(* Logix 5000 project; controller AMCI_3601_generic_sample_RSLogix_V28 vendor 1 type 14 code 108 rev 28.11; software revision 28.00 *)

TASK MainTask (continuous, watchdog 500 ms) : MainProgram

MODULES
   Local : vendor 1 type 14 code 108 (Compact 0, rev 28.11)
      AMCI_3601 : 1769-MODULE (Compact 1, rev 1.1, Output RPI 2 ms)
           Local:1:I.Data[3]   // AMCI 3601 lower current position
           Local:1:I.Data[2]   // AMCI 3601 upper current position
           Local:1:O.Data[1].9   // Blend Move Transmit bit
           Local:1:O.Data[0]   // AMCI 3601 module
END_MODULES

VAR_GLOBAL   (* controller tags *)
   blend_counter_3601 : COUNTER := (PRE := 6);   // control which blend segment is output to the 3601 module
        .PRE   // controls which blend programming block is output to the 3601 module
        .ACC   // controls which programming block is output
   blend_run_3601 : INT[8] := ([0] := 4096);
        [0]   // Run Blend Profile in the Positive Direction
   blend_segments_3601 : INT[17,8];
        [0,2]   // Number of segments
        [0,0]   // Blend Programming Block 1 Upper Command Word
        [1,1]   // Blend Programming Block 2, Lower Command Word
        [1,0]   // Blend Programming Block 2, Upper Command Word
        [0,4]   // Acceleration Type Segments 1 to 8
        [0,1]   // Blend Programming Block 1, Lower Command Word
        [1,2]   // Segment 1 upper target position
        [0,3]   // Acceleration Type segments 9 to 16
        [0,5]   // Final Segments Deceleration value and type
   buffered_3601_data : INT[8];
        [0].0   // AMCI 3601 motion occuring CW
        [0].14   // AMCI 3601 Module OK bit
        [0].7   // 3601 Move Compete bit
        [0].13   // AMCI 3601 configuration error
        [0].15   // AMCI 3601 mode bit 1=config mode 0=command mode
        [0].10   // AMCI 3601 position invalid bit
        [0].1   // AMCI 3601 motion occuring CCW
        [1].9   // The 3601 module sets this bit to Acknowledge the receipt of a blend move programming block
   CCW_Manual_Move_3601 : INT[8] := ([0] := 256, [4] := 2, [5] := 500, [6] := 10, [7] := 10);
   CCW_manual_move_occurring : BOOL;
   combined_position : DINT;
   comment : INT;   // used as output instruction on comment rungs
   configuration_3601 : INT[8] := ([0] := -31682, [1] := 62, [3] := 100);
        [3]   // Lower Starting Speed
        [0]   // Upper Configuration Word
        [2]   // Upper Starting Speed
        [1]   // Lower Configuration Word
   CW_manual_move_3601 : INT[8] := ([0] := 128, [4] := 1, [5] := 500, [6] := 10, [7] := 10);
   CW_manual_move_occurring : BOOL;
   Home_CW_3601 : INT[8] := ([0] := 32, [4] := 1, [6] := 10, [7] := 10);
   Least_Significant_Word : INT;
   Most_Significant_Word : INT;   // Most Significant Word
   one_shot_1 : BOOL;
   one_shot_2 : BOOL;
   original_value : DINT;
   preset_3601 : INT[8] := ([0] := 512);
        [0]   // Preset Position Command Word
        [2]   // Upper Preset Value
        [3]   // Lower Preset Value
        [1]   // Lower Command Word
   relative_CW_3601 : INT[8] := ([0] := 2, [2] := 5, [4] := 2, [6] := 10, [7] := 10);
        [0]   // Relative Move Command
        [1]   // Lower Command Word
        [3]   // Lower Target Position
        [4]   // Upper Programmed Speed
        [2]   // Upper Target Position
        [7]   // Deceleration
        [5]   // Lower Programmed Speed
        [6]   // Acceleration
   reset_errors_3601 : INT[8] := ([0] := 2048);
   run_3601 : INT;   // 1=run relative move 2=CW Manual Move 3=CCW Manual Move 4=reset errors 5=Home CW 6=Preset Position 7=Program Blend 8=Run Blend CW
   upper_resultX1000 : DINT;   // intermediate value
END_VAR

PROGRAM MainProgram   (* main routine MainRoutine *)

ROUTINE combine_separate   (* ladder *)
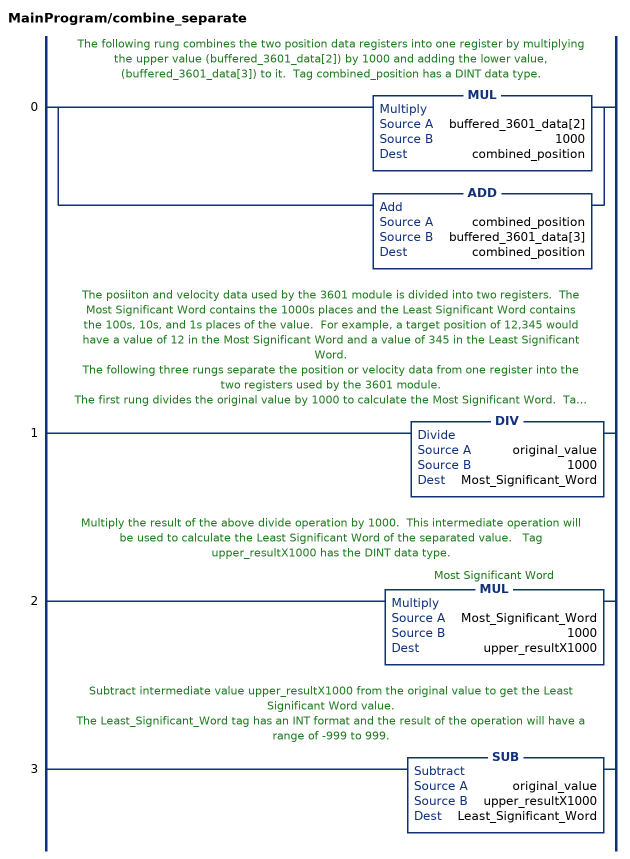
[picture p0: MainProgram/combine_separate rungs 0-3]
   // The following rung combines the two position data registers into one register by multiplying the upper value (buffered_3601_data[2]) by 1000 and adding the lower value, (buffered_3601_data[3]) to it.  Tag combined_position has a DINT data type.
   0: [MUL(buffered_3601_data[2],1000,combined_position) ,ADD(combined_position,buffered_3601_data[3],combined_position) ];
   // The posiiton and velocity data used by the 3601 module is divided into two registers.  The Most Significant Word contains the 1000s places and the Least Significant Word contains the 100s, 10s, and 1s places of the value.  For example, a target position of 12,345 would have a value of 12 in the Most Significant Word and a value of 345 in the Least Significant Word.
   // The following three rungs separate the position or velocity data from one register into the two registers used by the 3601 module.
   // The first rung divides the original value by 1000 to calculate the Most Significant Word.  Tag original_value must be in DINT format and tag Most_Significant_Word must be INT format.  Using these formats results in a truncated, not rounded, value.
   1: DIV(original_value,1000,Most_Significant_Word);
   // Multiply the result of the above divide operation by 1000.  This intermediate operation will be used to calculate the Least Significant Word of the separated value.   Tag upper_resultX1000 has the DINT data type.
   2: MUL(Most_Significant_Word,1000,upper_resultX1000);
   // Subtract intermediate value upper_resultX1000 from the original value to get the Least Significant Word value.
   // The Least_Significant_Word tag has an INT format and the result of the operation will have a range of -999 to 999.
   3: SUB(original_value,upper_resultX1000,Least_Significant_Word);
END_ROUTINE

ROUTINE MainRoutine   (* ladder *)
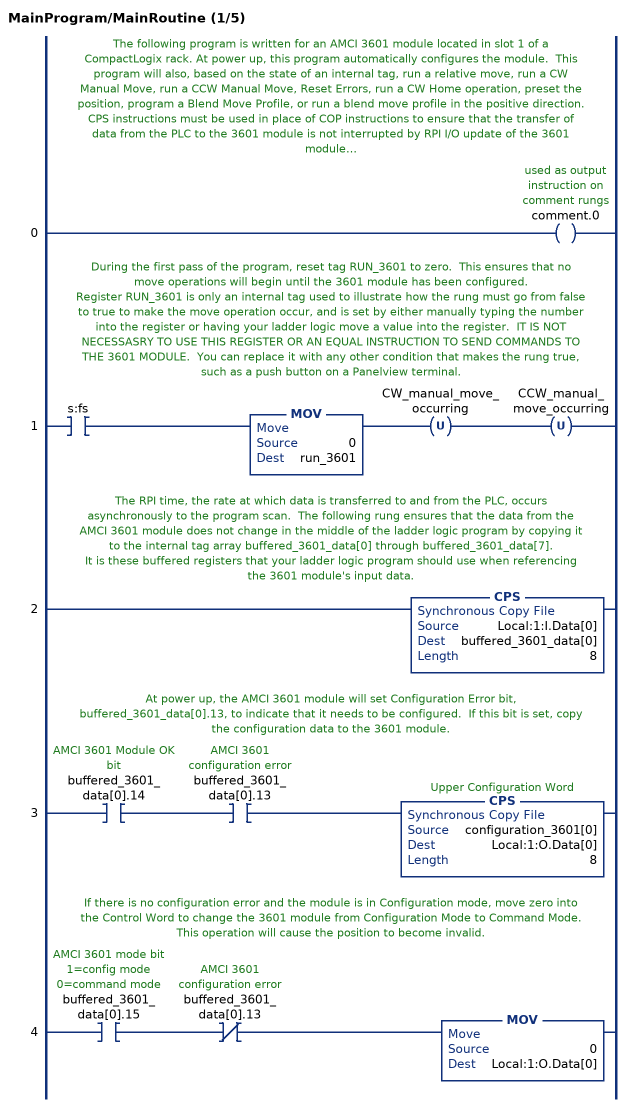
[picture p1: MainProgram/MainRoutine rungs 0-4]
   // The following program is written for an AMCI 3601 module located in slot 1 of a CompactLogix rack. At power up, this program automatically configures the module.  This program will also, based on the state of an internal tag, run a relative move, run a CW Manual Move, run a CCW Manual Move, Reset Errors, run a CW Home operation, preset the position, program a Blend Move Profile, or run a blend move profile in the positive direction.
   // CPS instructions must be used in place of COP instructions to ensure that the transfer of data from the PLC to the 3601 module is not interrupted by RPI I/O update of the 3601 module.
   // Subroutine combine_separate shows how to both combine the two position data words from the 3601 module into one tag, and also how to separate one tag value into the two word format used by the 3601 module.
   // Subroutine Program_Blend_3601 is used to program the 3601 module with up to sixteen blend segments, and is only necessary if you are using a blend profile in your stepper application.
   0: OTE(comment.0);
   // During the first pass of the program, reset tag RUN_3601 to zero.  This ensures that no move operations will begin until the 3601 module has been configured.
   // Register RUN_3601 is only an internal tag used to illustrate how the rung must go from false to true to make the move operation occur, and is set by either manually typing the number into the register or having your ladder logic move a value into the register.  IT IS NOT NECESSASRY TO USE THIS REGISTER OR AN EQUAL INSTRUCTION TO SEND COMMANDS TO THE 3601 MODULE.  You can replace it with any other condition that makes the rung true, such as a push button on a Panelview terminal.
   1: XIC(s:fs)MOV(0,run_3601)OTU(CW_manual_move_occurring)OTU(CCW_manual_move_occurring);
   // The RPI time, the rate at which data is transferred to and from the PLC, occurs asynchronously to the program scan.  The following rung ensures that the data from the AMCI 3601 module does not change in the middle of the ladder logic program by copying it to the internal tag array buffered_3601_data[0] through buffered_3601_data[7].
   // It is these buffered registers that your ladder logic program should use when referencing the 3601 module's input data.
   2: CPS(Local:1:I.Data[0],buffered_3601_data[0],8);
   // At power up, the AMCI 3601 module will set Configuration Error bit, buffered_3601_data[0].13, to indicate that it needs to be configured.  If this bit is set, copy the configuration data to the 3601 module.
   3: XIC(buffered_3601_data[0].14)XIC(buffered_3601_data[0].13)CPS(configuration_3601[0],Local:1:O.Data[0],8);
   // If there is no configuration error and the module is in Configuration mode, move zero into the Control Word to change the 3601 module from Configuration Mode to Command Mode.  This operation will cause the position to become invalid.
   4: XIC(buffered_3601_data[0].15)XIO(buffered_3601_data[0].13)MOV(0,Local:1:O.Data[0]);
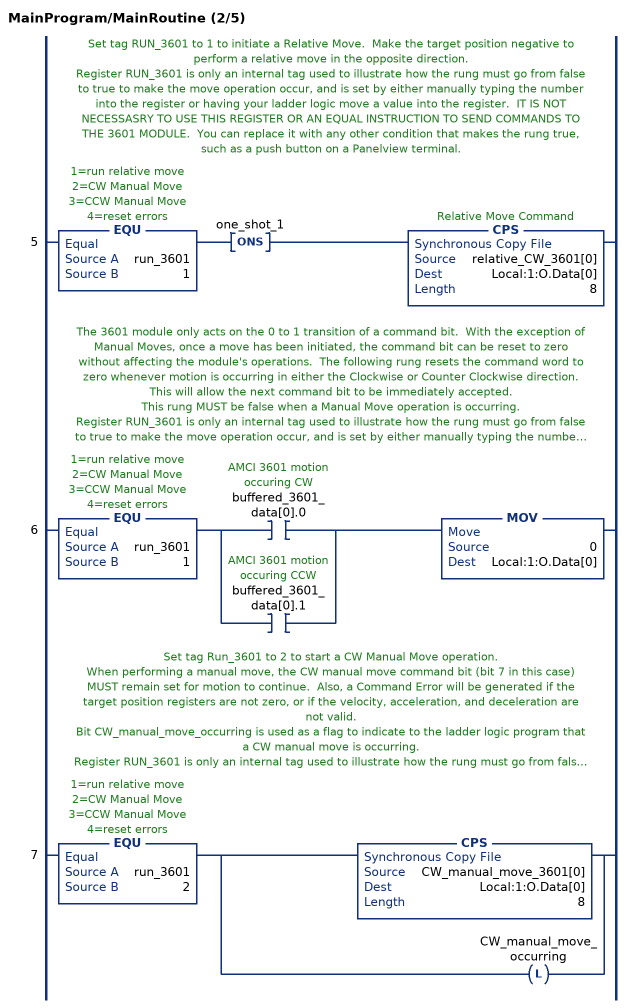
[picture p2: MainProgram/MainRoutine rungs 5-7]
   // Set tag RUN_3601 to 1 to initiate a Relative Move.  Make the target position negative to perform a relative move in the opposite direction.
   // Register RUN_3601 is only an internal tag used to illustrate how the rung must go from false to true to make the move operation occur, and is set by either manually typing the number into the register or having your ladder logic move a value into the register.  IT IS NOT NECESSASRY TO USE THIS REGISTER OR AN EQUAL INSTRUCTION TO SEND COMMANDS TO THE 3601 MODULE.  You can replace it with any other condition that makes the rung true, such as a push button on a Panelview terminal.
   5: EQU(run_3601,1)ONS(one_shot_1)CPS(relative_CW_3601[0],Local:1:O.Data[0],8);
   // The 3601 module only acts on the 0 to 1 transition of a command bit.  With the exception of Manual Moves, once a move has been initiated, the command bit can be reset to zero without affecting the module's operations.  The following rung resets the command word to zero whenever motion is occurring in either the Clockwise or Counter Clockwise direction.  This will allow the next command bit to be immediately accepted.
   // This rung MUST be false when a Manual Move operation is occurring.
   // Register RUN_3601 is only an internal tag used to illustrate how the rung must go from false to true to make the move operation occur, and is set by either manually typing the number into the register or having your ladder logic move a value into the register.  IT IS NOT NECESSASRY TO USE THIS REGISTER OR AN EQUAL INSTRUCTION TO SEND COMMANDS TO THE 3601 MODULE.  You can replace it with any other condition that makes the rung true, such as a push button on a Panelview terminal.
   6: EQU(run_3601,1)[XIC(buffered_3601_data[0].0) ,XIC(buffered_3601_data[0].1) ]MOV(0,Local:1:O.Data[0]);
   // Set tag Run_3601 to 2 to start a CW Manual Move operation.
   // When performing a manual move, the CW manual move command bit (bit 7 in this case) MUST remain set for motion to continue.  Also, a Command Error will be generated if the target position registers are not zero, or if the velocity, acceleration, and deceleration are not valid.
   // Bit CW_manual_move_occurring is used as a flag to indicate to the ladder logic program that a CW manual move is occurring.
   // Register RUN_3601 is only an internal tag used to illustrate how the rung must go from false to true to make the move operation occur, and is set by either manually typing the number into the register or having your ladder logic move a value into the register.  IT IS NOT NECESSASRY TO USE THIS REGISTER OR AN EQUAL INSTRUCTION TO SEND COMMANDS TO THE 3601 MODULE.  You can replace it with any other condition that makes the rung true, such as a push button on a Panelview terminal.
   7: EQU(run_3601,2)[CPS(CW_manual_move_3601[0],Local:1:O.Data[0],8) ,OTL(CW_manual_move_occurring) ];
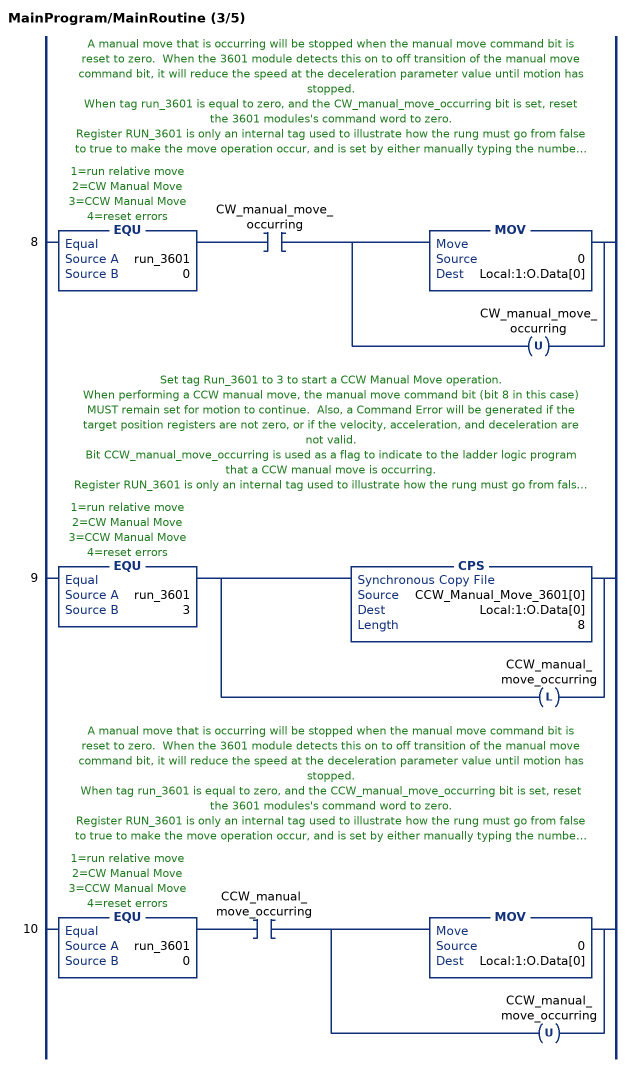
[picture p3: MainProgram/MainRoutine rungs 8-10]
   // A manual move that is occurring will be stopped when the manual move command bit is reset to zero.  When the 3601 module detects this on to off transition of the manual move command bit, it will reduce the speed at the deceleration parameter value until motion has stopped.
   // When tag run_3601 is equal to zero, and the CW_manual_move_occurring bit is set, reset the 3601 modules's command word to zero.
   // Register RUN_3601 is only an internal tag used to illustrate how the rung must go from false to true to make the move operation occur, and is set by either manually typing the number into the register or having your ladder logic move a value into the register.  IT IS NOT NECESSASRY TO USE THIS REGISTER OR AN EQUAL INSTRUCTION TO SEND COMMANDS TO THE 3601 MODULE.  You can replace it with any other condition that makes the rung true, such as a push button on a Panelview terminal.
   8: EQU(run_3601,0)XIC(CW_manual_move_occurring)[MOV(0,Local:1:O.Data[0]) ,OTU(CW_manual_move_occurring) ];
   // Set tag Run_3601 to 3 to start a CCW Manual Move operation.
   // When performing a CCW manual move, the manual move command bit (bit 8 in this case) MUST remain set for motion to continue.  Also, a Command Error will be generated if the target position registers are not zero, or if the velocity, acceleration, and deceleration are not valid.
   // Bit CCW_manual_move_occurring is used as a flag to indicate to the ladder logic program that a CCW manual move is occurring.
   // Register RUN_3601 is only an internal tag used to illustrate how the rung must go from false to true to make the move operation occur, and is set by either manually typing the number into the register or having your ladder logic move a value into the register.  IT IS NOT NECESSASRY TO USE THIS REGISTER OR AN EQUAL INSTRUCTION TO SEND COMMANDS TO THE 3601 MODULE.  You can replace it with any other condition that makes the rung true, such as a push button on a Panelview terminal.
   9: EQU(run_3601,3)[CPS(CCW_Manual_Move_3601[0],Local:1:O.Data[0],8) ,OTL(CCW_manual_move_occurring) ];
   // A manual move that is occurring will be stopped when the manual move command bit is reset to zero.  When the 3601 module detects this on to off transition of the manual move command bit, it will reduce the speed at the deceleration parameter value until motion has stopped.
   // When tag run_3601 is equal to zero, and the CCW_manual_move_occurring bit is set, reset the 3601 modules's command word to zero.
   // Register RUN_3601 is only an internal tag used to illustrate how the rung must go from false to true to make the move operation occur, and is set by either manually typing the number into the register or having your ladder logic move a value into the register.  IT IS NOT NECESSASRY TO USE THIS REGISTER OR AN EQUAL INSTRUCTION TO SEND COMMANDS TO THE 3601 MODULE.  You can replace it with any other condition that makes the rung true, such as a push button on a Panelview terminal.
   10: EQU(run_3601,0)XIC(CCW_manual_move_occurring)[MOV(0,Local:1:O.Data[0]) ,OTU(CCW_manual_move_occurring) ];
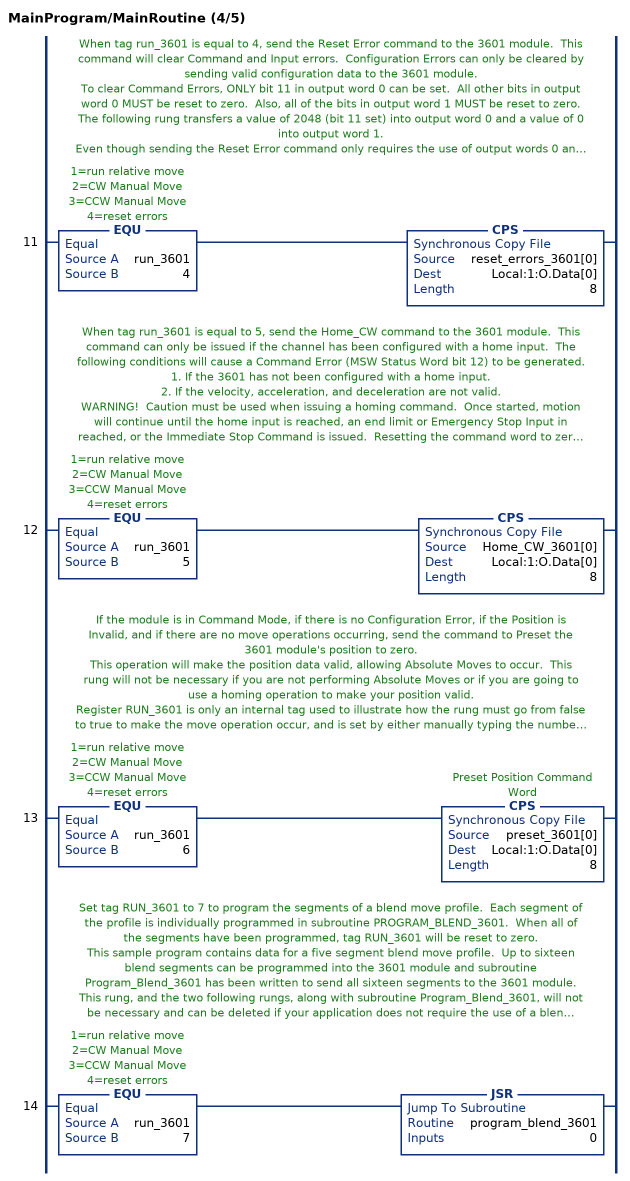
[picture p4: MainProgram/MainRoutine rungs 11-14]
   // When tag run_3601 is equal to 4, send the Reset Error command to the 3601 module.  This command will clear Command and Input errors.  Configuration Errors can only be cleared by sending valid configuration data to the 3601 module.
   // To clear Command Errors, ONLY bit 11 in output word 0 can be set.  All other bits in output word 0 MUST be reset to zero.  Also, all of the bits in output word 1 MUST be reset to zero.  The following rung transfers a value of 2048 (bit 11 set) into output word 0 and a value of 0 into output word 1.
   // Even though sending the Reset Error command only requires the use of output words 0 and 1, to keep the programming consistent the following rung also moves a value of zero into output words 2 through 7.
   // Register RUN_3601 is only an internal tag used to illustrate how the rung must go from false to true to make the move operation occur, and is set by either manually typing the number into the register or having your ladder logic move a value into the register.  IT IS NOT NECESSASRY TO USE THIS REGISTER OR AN EQUAL INSTRUCTION TO SEND COMMANDS TO THE 3601 MODULE.  You can replace it with any other condition that makes the rung true, such as a push button on a Panelview terminal.
   11: EQU(run_3601,4)CPS(reset_errors_3601[0],Local:1:O.Data[0],8);
   // When tag run_3601 is equal to 5, send the Home_CW command to the 3601 module.  This command can only be issued if the channel has been configured with a home input.  The following conditions will cause a Command Error (MSW Status Word bit 12) to be generated.
   // 1. If the 3601 has not been configured with a home input.
   // 2. If the velocity, acceleration, and deceleration are not valid.
   // WARNING!  Caution must be used when issuing a homing command.  Once started, motion will continue until the home input is reached, an end limit or Emergency Stop Input in reached, or the Immediate Stop Command is issued.  Resetting the command word to zero WILL NOT STOP a home operation.
   // Register RUN_3601 is only an internal tag used to illustrate how the rung must go from false to true to make the move operation occur, and is set by either manually typing the number into the register or having your ladder logic move a value into the register.  IT IS NOT NECESSASRY TO USE THIS REGISTER OR AN EQUAL INSTRUCTION TO SEND COMMANDS TO THE 3601 MODULE.  You can replace it with any other condition that makes the rung true, such as a push button on a Panelview terminal.
   12: EQU(run_3601,5)CPS(Home_CW_3601[0],Local:1:O.Data[0],8);
   // If the module is in Command Mode, if there is no Configuration Error, if the Position is Invalid, and if there are no move operations occurring, send the command to Preset the 3601 module's position to zero.
   // This operation will make the position data valid, allowing Absolute Moves to occur.  This rung will not be necessary if you are not performing Absolute Moves or if you are going to use a homing operation to make your position valid.
   // Register RUN_3601 is only an internal tag used to illustrate how the rung must go from false to true to make the move operation occur, and is set by either manually typing the number into the register or having your ladder logic move a value into the register.  IT IS NOT NECESSASRY TO USE THIS REGISTER OR AN EQUAL INSTRUCTION TO SEND COMMANDS TO THE 3601 MODULE.  You can replace it with any other condition that makes the rung true, such as a push button on a Panelview terminal.
   13: EQU(run_3601,6)CPS(preset_3601[0],Local:1:O.Data[0],8);
   // Set tag RUN_3601 to 7 to program the segments of a blend move profile.  Each segment of the profile is individually programmed in subroutine PROGRAM_BLEND_3601.  When all of the segments have been programmed, tag RUN_3601 will be reset to zero.
   // This sample program contains data for a five segment blend move profile.  Up to sixteen blend segments can be programmed into the 3601 module and subroutine Program_Blend_3601 has been written to send all sixteen segments to the 3601 module.
   // This rung, and the two following rungs, along with subroutine Program_Blend_3601, will not be necessary and can be deleted if your application does not require the use of a blend move profile.
   // Register RUN_3601 is only an internal tag used to illustrate how the rung must go from false to true to make the move operation occur, and is set by either manually typing the number into the register or having your ladder logic move a value into the register.  IT IS NOT NECESSASRY TO USE THIS REGISTER OR AN EQUAL INSTRUCTION TO SEND COMMANDS TO THE 3601 MODULE.  You can replace it with any other condition that makes the rung true, such as a push button on a Panelview terminal.
   14: EQU(run_3601,7)JSR(program_blend_3601,0);
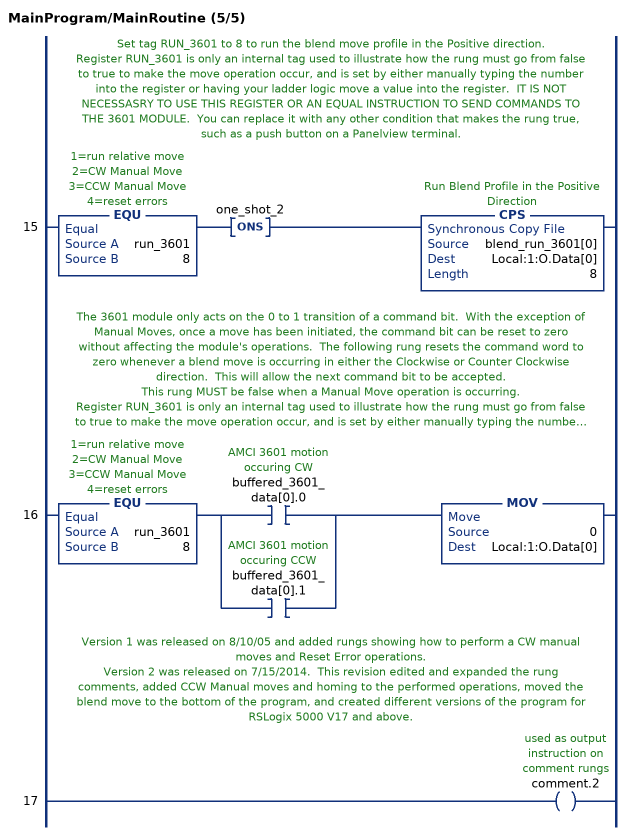
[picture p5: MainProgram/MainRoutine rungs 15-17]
   // Set tag RUN_3601 to 8 to run the blend move profile in the Positive direction.
   // Register RUN_3601 is only an internal tag used to illustrate how the rung must go from false to true to make the move operation occur, and is set by either manually typing the number into the register or having your ladder logic move a value into the register.  IT IS NOT NECESSASRY TO USE THIS REGISTER OR AN EQUAL INSTRUCTION TO SEND COMMANDS TO THE 3601 MODULE.  You can replace it with any other condition that makes the rung true, such as a push button on a Panelview terminal.
   15: EQU(run_3601,8)ONS(one_shot_2)CPS(blend_run_3601[0],Local:1:O.Data[0],8);
   // The 3601 module only acts on the 0 to 1 transition of a command bit.  With the exception of Manual Moves, once a move has been initiated, the command bit can be reset to zero without affecting the module's operations.  The following rung resets the command word to zero whenever a blend move is occurring in either the Clockwise or Counter Clockwise direction.  This will allow the next command bit to be accepted.
   // This rung MUST be false when a Manual Move operation is occurring.
   // Register RUN_3601 is only an internal tag used to illustrate how the rung must go from false to true to make the move operation occur, and is set by either manually typing the number into the register or having your ladder logic move a value into the register.  IT IS NOT NECESSASRY TO USE THIS REGISTER OR AN EQUAL INSTRUCTION TO SEND COMMANDS TO THE 3601 MODULE.  You can replace it with any other condition that makes the rung true, such as a push button on a Panelview terminal.
   16: EQU(run_3601,8)[XIC(buffered_3601_data[0].0) ,XIC(buffered_3601_data[0].1) ]MOV(0,Local:1:O.Data[0]);
   // Version 1 was released on 8/10/05 and added rungs showing how to perform a CW manual moves and Reset Error operations.
   // Version 2 was released on 7/15/2014.  This revision edited and expanded the rung comments, added CCW Manual moves and homing to the performed operations, moved the blend move to the bottom of the program, and created different versions of the program for RSLogix 5000 V17 and above.
   17: OTE(comment.2);
END_ROUTINE

ROUTINE program_blend_3601   (* ladder *)
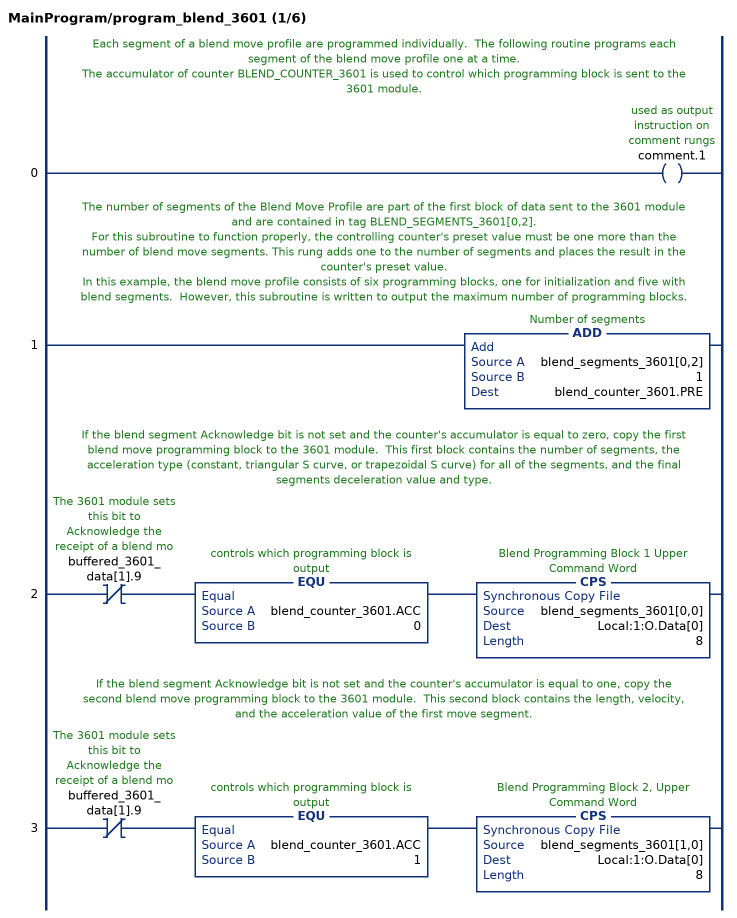
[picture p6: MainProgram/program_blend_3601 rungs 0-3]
   // Each segment of a blend move profile are programmed individually.  The following routine programs each segment of the blend move profile one at a time.
   // The accumulator of counter BLEND_COUNTER_3601 is used to control which programming block is sent to the 3601 module.
   0: OTE(comment.1);
   // The number of segments of the Blend Move Profile are part of the first block of data sent to the 3601 module and are contained in tag BLEND_SEGMENTS_3601[0,2].
   // For this subroutine to function properly, the controlling counter's preset value must be one more than the number of blend move segments. This rung adds one to the number of segments and places the result in the counter's preset value.
   // In this example, the blend move profile consists of six programming blocks, one for initialization and five with blend segments.  However, this subroutine is written to output the maximum number of programming blocks.
   1: ADD(blend_segments_3601[0,2],1,blend_counter_3601.PRE);
   // If the blend segment Acknowledge bit is not set and the counter's accumulator is equal to zero, copy the first blend move programming block to the 3601 module.  This first block contains the number of segments, the acceleration type (constant, triangular S curve, or trapezoidal S curve) for all of the segments, and the final segments deceleration value and type.
   2: XIO(buffered_3601_data[1].9)EQU(blend_counter_3601.ACC,0)CPS(blend_segments_3601[0,0],Local:1:O.Data[0],8);
   // If the blend segment Acknowledge bit is not set and the counter's accumulator is equal to one, copy the second blend move programming block to the 3601 module.  This second block contains the length, velocity, and the acceleration value of the first move segment.
   3: XIO(buffered_3601_data[1].9)EQU(blend_counter_3601.ACC,1)CPS(blend_segments_3601[1,0],Local:1:O.Data[0],8);
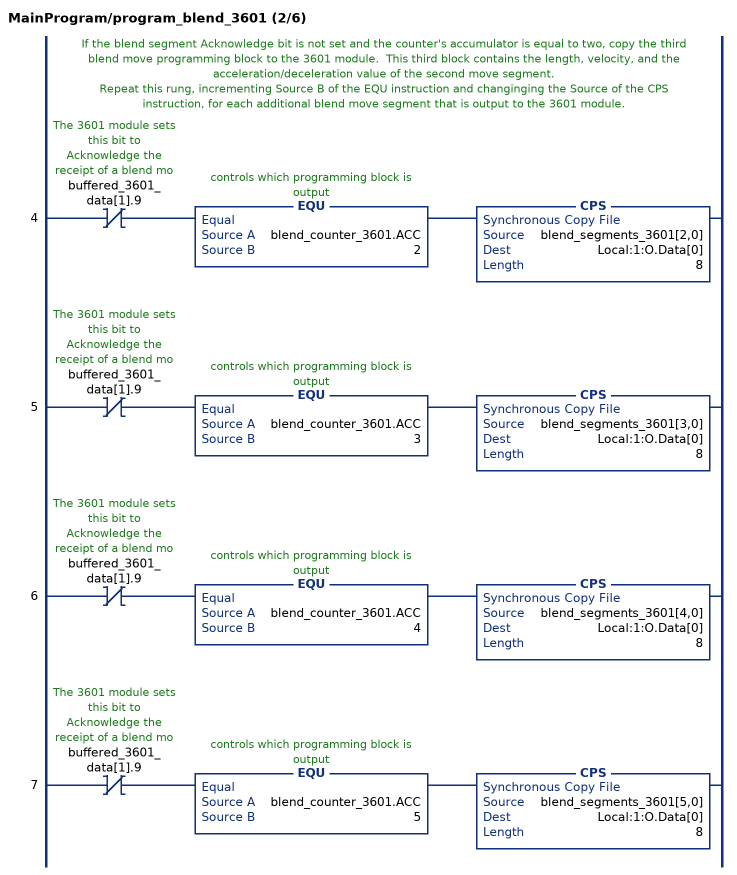
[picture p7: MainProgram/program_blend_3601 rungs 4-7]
   // If the blend segment Acknowledge bit is not set and the counter's accumulator is equal to two, copy the third blend move programming block to the 3601 module.  This third block contains the length, velocity, and the acceleration/deceleration value of the second move segment.
   // Repeat this rung, incrementing Source B of the EQU instruction and changinging the Source of the CPS instruction, for each additional blend move segment that is output to the 3601 module.
   4: XIO(buffered_3601_data[1].9)EQU(blend_counter_3601.ACC,2)CPS(blend_segments_3601[2,0],Local:1:O.Data[0],8);
   5: XIO(buffered_3601_data[1].9)EQU(blend_counter_3601.ACC,3)CPS(blend_segments_3601[3,0],Local:1:O.Data[0],8);
   6: XIO(buffered_3601_data[1].9)EQU(blend_counter_3601.ACC,4)CPS(blend_segments_3601[4,0],Local:1:O.Data[0],8);
   7: XIO(buffered_3601_data[1].9)EQU(blend_counter_3601.ACC,5)CPS(blend_segments_3601[5,0],Local:1:O.Data[0],8);
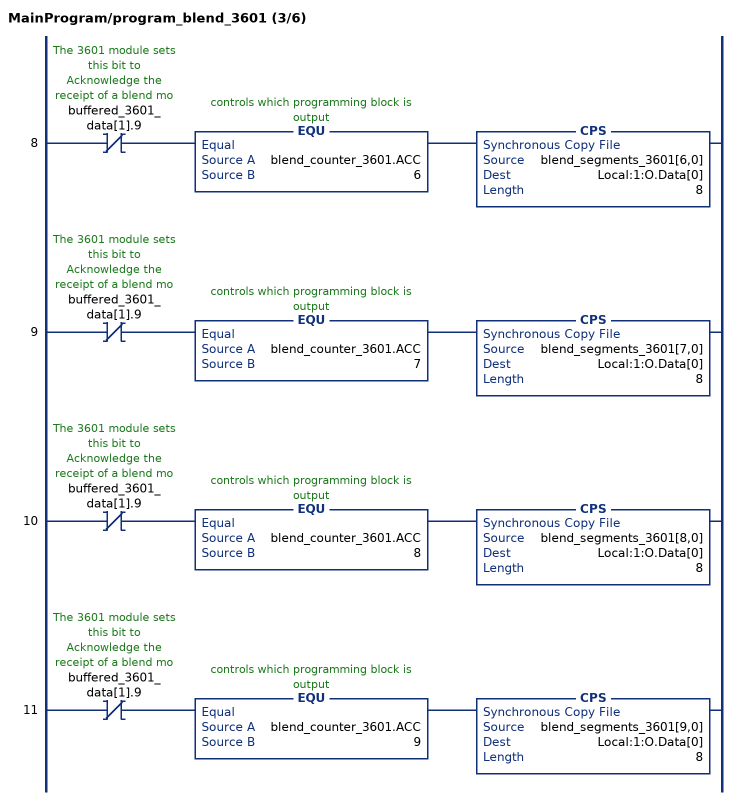
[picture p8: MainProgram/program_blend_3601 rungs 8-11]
   8: XIO(buffered_3601_data[1].9)EQU(blend_counter_3601.ACC,6)CPS(blend_segments_3601[6,0],Local:1:O.Data[0],8);
   9: XIO(buffered_3601_data[1].9)EQU(blend_counter_3601.ACC,7)CPS(blend_segments_3601[7,0],Local:1:O.Data[0],8);
   10: XIO(buffered_3601_data[1].9)EQU(blend_counter_3601.ACC,8)CPS(blend_segments_3601[8,0],Local:1:O.Data[0],8);
   11: XIO(buffered_3601_data[1].9)EQU(blend_counter_3601.ACC,9)CPS(blend_segments_3601[9,0],Local:1:O.Data[0],8);
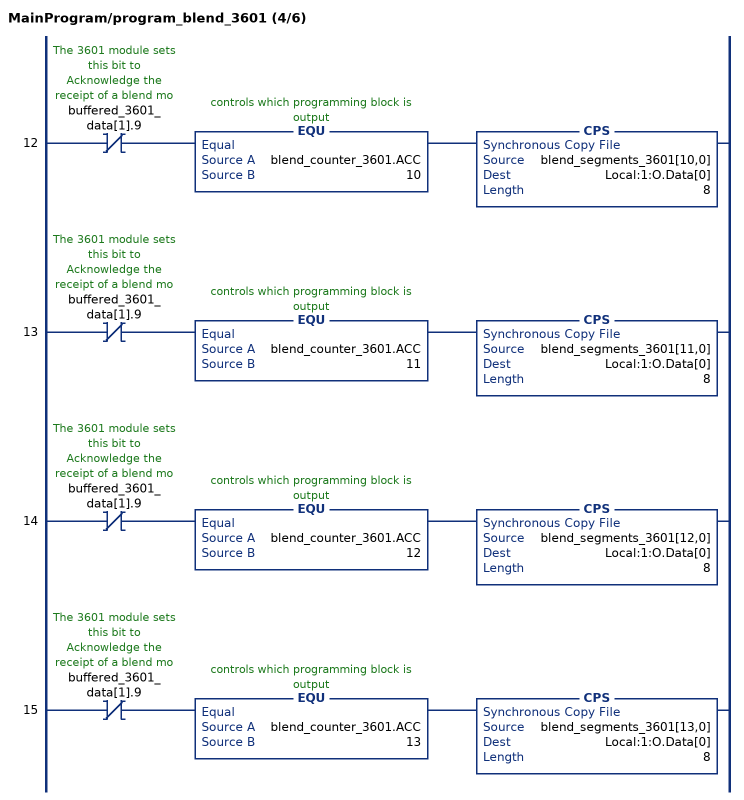
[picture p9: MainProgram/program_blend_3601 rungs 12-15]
   12: XIO(buffered_3601_data[1].9)EQU(blend_counter_3601.ACC,10)CPS(blend_segments_3601[10,0],Local:1:O.Data[0],8);
   13: XIO(buffered_3601_data[1].9)EQU(blend_counter_3601.ACC,11)CPS(blend_segments_3601[11,0],Local:1:O.Data[0],8);
   14: XIO(buffered_3601_data[1].9)EQU(blend_counter_3601.ACC,12)CPS(blend_segments_3601[12,0],Local:1:O.Data[0],8);
   15: XIO(buffered_3601_data[1].9)EQU(blend_counter_3601.ACC,13)CPS(blend_segments_3601[13,0],Local:1:O.Data[0],8);
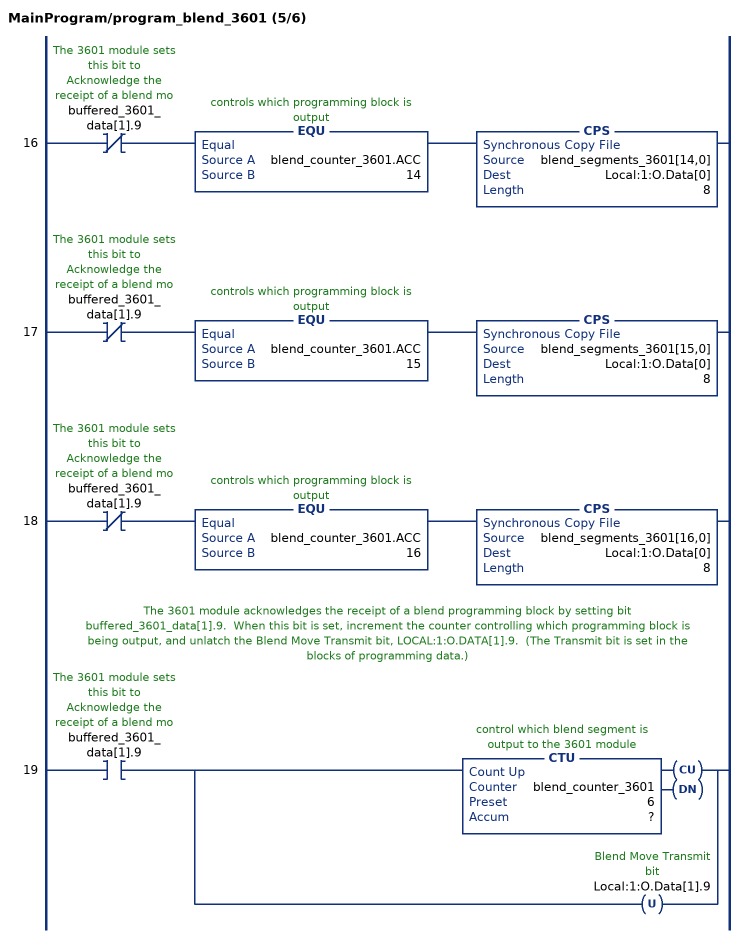
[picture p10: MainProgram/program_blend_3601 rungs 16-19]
   16: XIO(buffered_3601_data[1].9)EQU(blend_counter_3601.ACC,14)CPS(blend_segments_3601[14,0],Local:1:O.Data[0],8);
   17: XIO(buffered_3601_data[1].9)EQU(blend_counter_3601.ACC,15)CPS(blend_segments_3601[15,0],Local:1:O.Data[0],8);
   18: XIO(buffered_3601_data[1].9)EQU(blend_counter_3601.ACC,16)CPS(blend_segments_3601[16,0],Local:1:O.Data[0],8);
   // The 3601 module acknowledges the receipt of a blend programming block by setting bit buffered_3601_data[1].9.  When this bit is set, increment the counter controlling which programming block is being output, and unlatch the Blend Move Transmit bit, LOCAL:1:O.DATA[1].9.  (The Transmit bit is set in the blocks of programming data.)
   19: XIC(buffered_3601_data[1].9)[CTU(blend_counter_3601,?,?) ,OTU(Local:1:O.Data[1].9) ];
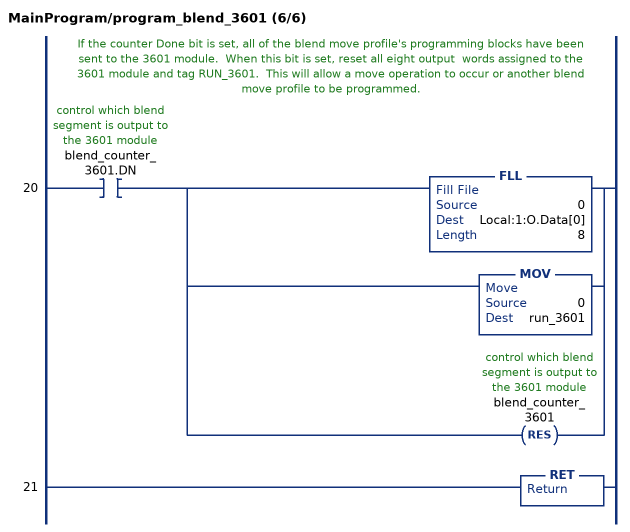
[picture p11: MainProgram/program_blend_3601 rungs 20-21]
   // If the counter Done bit is set, all of the blend move profile's programming blocks have been sent to the 3601 module.  When this bit is set, reset all eight output  words assigned to the 3601 module and tag RUN_3601.  This will allow a move operation to occur or another blend move profile to be programmed.
   20: XIC(blend_counter_3601.DN)[FLL(0,Local:1:O.Data[0],8) ,MOV(0,run_3601) ,RES(blend_counter_3601) ];
   21: RET();
END_ROUTINE
END_PROGRAM
